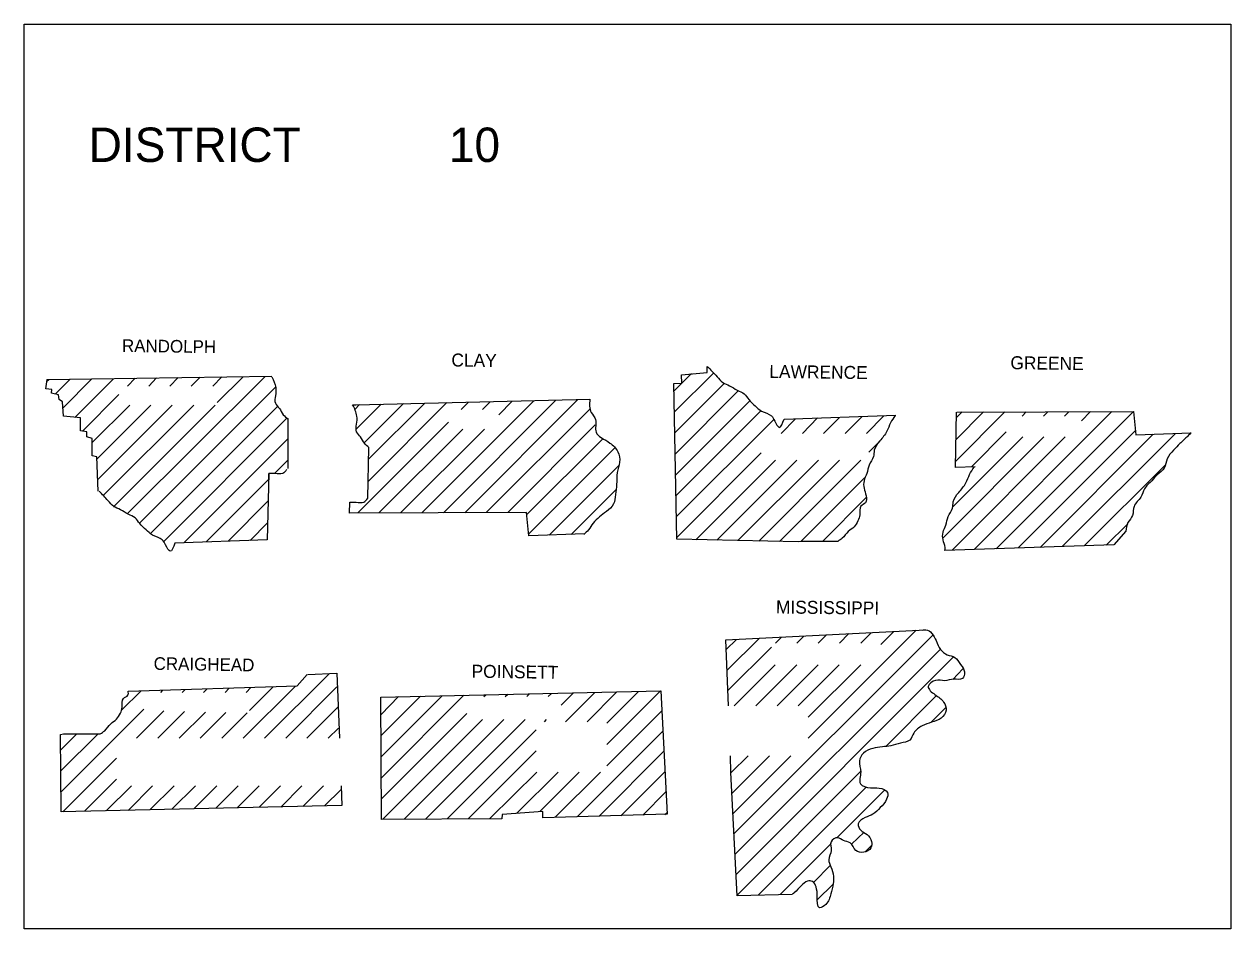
# Model space of a CAD drawing. Extents: x 23481 to 28196, y 1325020 to 1327623.
# Drawn here: x 27792.5 to 28192.5, y 1325389.6 to 1325689.6 of the extents above; entities that cross this region are included whole.
import ezdxf

# ---------------------------------------------------------------- set-up
doc = ezdxf.new("R2010")
doc.units = 0
doc.layers.add('S_ELECTRIC_UTILITIES_ANNOT', color=7, linetype='Continuous')

msp = doc.modelspace()

# ---------------------------------------------------------------- linework, layer by layer
at = {"layer": 'S_ELECTRIC_UTILITIES_ANNOT'}
msp.add_lwpolyline([(27792.46, 1325389.62), (27792.46, 1325689.62), (28192.46, 1325689.62), (28192.46, 1325389.62)], close=True, dxfattribs=at)
for points in [[(28049.06, 1325517.92), (28008.76, 1325518.82), (28007.86, 1325570.42), (28010.46, 1325570.52), (28010.36, 1325573.32), (28018.86, 1325574.12), (28018.86, 1325576.12)], [(27799.96, 1325571.82), (27874.56, 1325572.92)], [(27805.36, 1325562.42), (27814.86, 1325572.02)], [(27809.26, 1325559.22), (27822.06, 1325572.02)], [(27826.76, 1325527.32), (27872.36, 1325572.82)], [(27826.76, 1325569.62), (27829.26, 1325572.22)], [(27833.76, 1325569.62), (27836.36, 1325572.32)], [(27840.76, 1325569.62), (27843.56, 1325572.42)], [(27847.86, 1325569.62), (27850.76, 1325572.52)], [(27854.96, 1325569.62), (27857.96, 1325572.62)], [(27856.46, 1325564.12), (27865.06, 1325572.72)], [(28007.86, 1325567.92), (28010.46, 1325570.52), (28013.66, 1325573.72)], [(28008.06, 1325561.02), (28020.96, 1325573.92)], [(27816.96, 1325534.72), (27816.56, 1325546.12), (27814.96, 1325546.42), (27815.06, 1325552.22), (27813.26, 1325552.72), (27813.26, 1325554.42), (27811.16, 1325554.72), (27811.16, 1325559.02), (27805.46, 1325559.62), (27805.16, 1325564.42), (27804.06, 1325565.12), (27803.86, 1325566.72), (27801.56, 1325567.22), (27801.66, 1325568.42), (27799.66, 1325568.72), (27800.06, 1325571.82)], [(27799.96, 1325571.22), (27800.66, 1325571.82)], [(27802.86, 1325567.02), (27807.76, 1325571.92)], [(27830.76, 1325524.22), (27875.76, 1325569.22)], [(28008.16, 1325554.12), (28024.46, 1325570.42)], [(28008.36, 1325547.12), (28029.16, 1325568.02)], [(27811.76, 1325554.62), (27823.86, 1325566.82)], [(27901.36, 1325563.42), (27902.36, 1325563.42), (27979.96, 1325565.22)], [(27906.56, 1325538.12), (27932.56, 1325564.12)], [(27924.26, 1325527.52), (27961.46, 1325564.72)], [(27931.46, 1325527.62), (27968.76, 1325564.92)], [(27937.36, 1325561.82), (27939.76, 1325564.22)], [(27938.56, 1325527.62), (27975.96, 1325565.12)], [(27944.36, 1325561.82), (27946.96, 1325564.42)], [(27949.76, 1325560.12), (27954.26, 1325564.62)], [(28008.46, 1325540.22), (28032.96, 1325564.72)], [(27815.06, 1325550.92), (27827.46, 1325563.32)], [(27816.66, 1325545.52), (27834.46, 1325563.32)], [(27816.86, 1325538.62), (27841.56, 1325563.32)], [(27818.76, 1325533.42), (27848.66, 1325563.32)], [(27822.06, 1325529.62), (27822.16, 1325529.72), (27855.76, 1325563.32)], [(27834.46, 1325520.82), (27876.46, 1325562.82)], [(27902.06, 1325561.82), (27903.66, 1325563.52)], [(27902.66, 1325555.42), (27910.86, 1325563.62)], [(27905.16, 1325550.82), (27918.16, 1325563.82)], [(27906.66, 1325545.32), (27925.26, 1325563.92)], [(27945.66, 1325527.72), (27980.16, 1325562.22)], [(28008.56, 1325533.32), (28036.66, 1325561.42)], [(28101.16, 1325544.62), (28117.56, 1325561.02)], [(28101.16, 1325542.62), (28101.56, 1325560.92)], [(28101.36, 1325551.92), (28110.46, 1325561.02)], [(28101.56, 1325559.22), (28103.36, 1325561.02)], [(28101.66, 1325560.92), (28160.16, 1325561.22), (28160.96, 1325553.42), (28179.26, 1325554.12)], [(28107.36, 1325515.42), (28152.96, 1325561.12)], [(28114.66, 1325515.62), (28160.16, 1325561.22)], [(28123.26, 1325559.62), (28124.56, 1325561.02)], [(28130.36, 1325559.62), (28131.76, 1325561.02)], [(28137.36, 1325559.62), (28138.76, 1325561.02)], [(28142.96, 1325558.12), (28145.96, 1325561.12)], [(27838.76, 1325518.12), (27879.56, 1325558.92)], [(27879.86, 1325558.52), (27879.86, 1325542.22)], [(27903.06, 1325527.52), (27933.16, 1325557.62)], [(27952.76, 1325527.72), (27981.76, 1325556.72)], [(28008.66, 1325526.32), (28040.96, 1325558.52)], [(28043.36, 1325553.92), (28048.16, 1325558.72)], [(28044.36, 1325558.62), (28081.46, 1325559.92)], [(28050.46, 1325553.92), (28055.46, 1325559.02)], [(28057.46, 1325553.92), (28062.76, 1325559.22)], [(28064.66, 1325553.92), (28070.16, 1325559.42)], [(28071.66, 1325553.92), (28077.46, 1325559.72)], [(27845.46, 1325517.72), (27879.86, 1325552.12)], [(27910.06, 1325527.52), (27937.86, 1325555.32)], [(27917.26, 1325527.52), (27945.06, 1325555.32)], [(27959.06, 1325527.02), (27984.26, 1325552.12)], [(28097.06, 1325519.32), (28130.46, 1325552.72)], [(28100.06, 1325515.22), (28137.56, 1325552.72)], [(28100.36, 1325529.72), (28123.46, 1325552.72)], [(28106.46, 1325542.82), (28117.96, 1325554.42)], [(28121.96, 1325515.92), (28160.76, 1325554.72)], [(28129.26, 1325516.12), (28166.76, 1325553.62)], [(28136.56, 1325516.42), (28174.06, 1325553.92)], [(27906.36, 1325532.42), (27906.76, 1325549.22)], [(27959.76, 1325520.62), (27988.26, 1325549.12)], [(28072.46, 1325547.72), (28075.66, 1325550.92)], [(27875.46, 1325540.62), (27879.86, 1325545.02)], [(28008.76, 1325519.42), (28036.76, 1325547.42)], [(28015.16, 1325518.62), (28041.56, 1325545.02)], [(28022.06, 1325518.52), (28048.56, 1325545.02)], [(28029.06, 1325518.42), (28055.76, 1325545.02)], [(28035.96, 1325518.22), (28062.76, 1325545.02)], [(28042.86, 1325518.12), (28069.76, 1325545.02)], [(27873.56, 1325536.92), (27873.56, 1325540.62), (27873.06, 1325518.62)], [(27966.46, 1325520.22), (27989.56, 1325543.32)], [(28107.66, 1325542.82), (28101.16, 1325542.62)], [(28143.86, 1325516.62), (28170.66, 1325543.42)], [(27852.76, 1325517.92), (27873.56, 1325538.72), (27873.56, 1325538.72)], [(28049.96, 1325518.12), (28071.06, 1325539.22)], [(27973.76, 1325520.42), (27988.66, 1325535.32)], [(28057.06, 1325518.12), (28071.56, 1325532.62)], [(27860.06, 1325518.22), (27873.36, 1325531.52)], [(27900.36, 1325527.42), (27900.46, 1325531.12)], [(27867.36, 1325518.42), (27873.16, 1325524.22)], [(27978.16, 1325520.62), (27959.76, 1325519.92), (27958.96, 1325527.72), (27900.46, 1325527.42)], [(28157.66, 1325521.52), (28153.66, 1325516.92), (28097.66, 1325515.12)], [(28151.16, 1325516.82), (28158.26, 1325523.92)], [(27873.06, 1325518.62), (27842.46, 1325517.52)], [(28062.16, 1325518.12), (28049.96, 1325518.12), (28049.06, 1325517.92)], [(28025.06, 1325485.42), (28091.36, 1325488.82)], [(28052.36, 1325452.82), (28088.16, 1325488.62)], [(28076.46, 1325483.92), (28080.76, 1325488.22)], [(28025.96, 1325463.62), (28025.06, 1325485.42)], [(28025.16, 1325482.22), (28028.56, 1325485.62)], [(28025.46, 1325475.42), (28036.06, 1325485.92)], [(28027.76, 1325421.12), (28093.56, 1325486.92), (28093.66, 1325487.02)], [(28041.56, 1325484.32), (28043.56, 1325486.32)], [(28048.56, 1325484.32), (28050.96, 1325486.72)], [(28055.66, 1325484.32), (28058.46, 1325487.12)], [(28062.76, 1325484.32), (28065.86, 1325487.52)], [(28069.76, 1325484.32), (28073.26, 1325487.82)], [(28025.76, 1325468.62), (28040.16, 1325483.02)], [(28028.06, 1325414.32), (28096.16, 1325482.42)], [(28027.86, 1325463.62), (28041.46, 1325477.22)], [(28028.46, 1325407.62), (28100.56, 1325479.82)], [(28034.96, 1325463.62), (28048.56, 1325477.22)], [(28042.06, 1325463.62), (28055.66, 1325477.22)], [(28049.06, 1325463.62), (28062.66, 1325477.22)], [(28052.36, 1325459.82), (28069.76, 1325477.22)], [(27826.96, 1325468.42), (27882.96, 1325470.22), (27886.26, 1325474.02)], [(27872.16, 1325452.82), (27893.56, 1325474.22)], [(27886.46, 1325473.92), (27896.06, 1325474.42)], [(27896.06, 1325474.42), (27896.96, 1325452.82)], [(28100.26, 1325472.32), (28103.66, 1325475.82)], [(27824.76, 1325462.12), (27831.26, 1325468.52)], [(27837.76, 1325468.02), (27838.46, 1325468.72)], [(27844.86, 1325468.02), (27845.76, 1325468.92)], [(27851.96, 1325468.02), (27853.16, 1325469.22)], [(27859.06, 1325468.02), (27860.46, 1325469.42)], [(27865.06, 1325452.82), (27882.36, 1325470.12)], [(27866.06, 1325468.02), (27867.66, 1325469.62)], [(27867.16, 1325462.02), (27875.06, 1325469.92)], [(27879.16, 1325452.82), (27896.16, 1325469.92)], [(27910.66, 1325466.42), (28003.56, 1325468.52)], [(27971.96, 1325458.32), (27981.66, 1325468.02)], [(27979.06, 1325458.32), (27988.96, 1325468.22)], [(27985.56, 1325450.72), (28003.36, 1325468.52)], [(27985.56, 1325457.82), (27996.16, 1325468.32)], [(28003.56, 1325468.52), (28005.56, 1325427.62)], [(27910.96, 1325425.92), (27910.66, 1325466.42)], [(27910.76, 1325453.72), (27923.86, 1325466.82)], [(27910.76, 1325460.72), (27916.56, 1325466.62)], [(27910.86, 1325446.72), (27931.06, 1325466.92)], [(27910.96, 1325439.72), (27938.26, 1325467.12)], [(27944.86, 1325466.62), (27945.46, 1325467.22)], [(27951.96, 1325466.62), (27952.76, 1325467.42)], [(27959.06, 1325466.62), (27959.96, 1325467.52)], [(27966.16, 1325466.62), (27967.26, 1325467.72)], [(27970.46, 1325463.82), (27974.46, 1325467.82)], [(28078.06, 1325450.12), (28094.76, 1325466.92)], [(27804.76, 1325435.02), (27832.16, 1325462.42)], [(27829.66, 1325452.82), (27838.76, 1325461.92)], [(27836.76, 1325452.82), (27845.66, 1325461.72)], [(27843.86, 1325452.82), (27852.56, 1325461.52)], [(27850.86, 1325452.82), (27859.36, 1325461.32)], [(27857.96, 1325452.82), (27866.36, 1325461.22)], [(27886.16, 1325452.82), (27896.46, 1325463.12)], [(27910.96, 1325432.72), (27939.26, 1325461.02)], [(27985.56, 1325443.72), (28003.86, 1325461.92)], [(28092.96, 1325458.02), (28097.96, 1325463.02)], [(27893.26, 1325452.82), (27896.66, 1325456.22)], [(27911.36, 1325426.02), (27944.36, 1325459.02)], [(27918.46, 1325426.02), (27951.46, 1325459.02)], [(27925.46, 1325426.02), (27958.56, 1325459.02)], [(27964.96, 1325458.32), (27965.66, 1325459.02)], [(27804.56, 1325454.12), (27805.46, 1325454.32), (27817.66, 1325454.32)], [(27804.76, 1325428.42), (27804.56, 1325454.12)], [(27804.66, 1325442.02), (27816.96, 1325454.32)], [(27804.66, 1325449.02), (27809.96, 1325454.32)], [(27932.66, 1325426.12), (27962.16, 1325455.62)], [(27975.76, 1325426.82), (28004.16, 1325455.22)], [(27939.66, 1325426.12), (27962.16, 1325448.62)], [(27982.96, 1325426.92), (28004.56, 1325448.52)], [(27805.26, 1325428.42), (27823.06, 1325446.22)], [(28028.76, 1325400.62), (28026.76, 1325441.52), (28026.56, 1325447.02)], [(28026.86, 1325441.42), (28032.46, 1325447.02)], [(28027.16, 1325434.62), (28039.56, 1325447.02)], [(28027.46, 1325427.92), (28046.56, 1325447.02)], [(27946.76, 1325426.12), (27962.36, 1325441.62)], [(27955.66, 1325427.92), (27969.46, 1325441.62)], [(27963.36, 1325428.52), (27976.46, 1325441.62)], [(27968.46, 1325426.62), (27983.56, 1325441.62)], [(27990.26, 1325427.12), (28004.86, 1325441.72)], [(28028.76, 1325400.82), (28069.66, 1325441.82)], [(27812.46, 1325428.62), (27823.06, 1325439.22)], [(27819.66, 1325428.72), (27828.06, 1325437.02)], [(27826.96, 1325428.92), (27835.06, 1325437.02)], [(27834.16, 1325429.12), (27842.16, 1325437.02)], [(27841.46, 1325429.32), (27849.26, 1325437.02)], [(27848.66, 1325429.42), (27856.36, 1325437.02)], [(27855.96, 1325429.62), (27863.36, 1325437.02)], [(27863.16, 1325429.82), (27870.36, 1325437.02)], [(27870.36, 1325429.92), (27877.46, 1325437.02)], [(27877.56, 1325430.02), (27884.56, 1325437.02)], [(27884.86, 1325430.22), (27891.66, 1325437.02)], [(27897.56, 1325437.02), (27897.76, 1325430.52)], [(28035.76, 1325400.82), (28071.56, 1325436.62)], [(27892.06, 1325430.42), (27897.56, 1325435.82)], [(27997.56, 1325427.32), (28005.16, 1325435.02)], [(28061.96, 1325419.92), (28077.76, 1325435.72)], [(27897.76, 1325430.52), (27804.76, 1325428.42)], [(28005.56, 1325427.62), (27964.36, 1325426.42), (27964.36, 1325428.52), (27950.96, 1325427.52), (27950.86, 1325426.12), (27910.96, 1325425.92)], [(28004.86, 1325427.52), (28005.56, 1325428.22)], [(28066.76, 1325417.72), (28070.86, 1325421.72)], [(28043.06, 1325401.02), (28059.96, 1325417.92)], [(28071.36, 1325415.22), (28073.36, 1325417.22)], [(28054.16, 1325405.02), (28059.76, 1325410.72)], [(28055.36, 1325399.22), (28060.66, 1325404.42)], [(28047.06, 1325401.02), (28028.76, 1325400.62)]]:
    msp.add_lwpolyline(points, dxfattribs=at)
for points in [[(28018.86, 1325576.12), (28022.16, 1325572.72), (28024.06, 1325570.82), (28026.26, 1325569.72), (28028.86, 1325568.22), (28031.16, 1325567.02), (28032.66, 1325565.12), (28034.76, 1325563.02), (28036.86, 1325561.32), (28040.16, 1325559.72), (28041.26, 1325558.02), (28042.76, 1325555.92), (28044.36, 1325558.62)], [(27874.56, 1325572.62), (27875.86, 1325569.12), (27875.76, 1325566.42), (27875.76, 1325563.92), (27877.06, 1325562.22), (27878.36, 1325560.12), (27880.06, 1325558.62)], [(27979.96, 1325565.22), (27980.46, 1325560.82), (27981.86, 1325558.52), (27982.06, 1325554.32), (27983.76, 1325552.52), (27986.66, 1325550.72), (27989.26, 1325547.82), (27989.86, 1325544.42), (27989.06, 1325540.92), (27988.86, 1325537.02), (27988.46, 1325533.62), (27987.86, 1325530.52), (27985.46, 1325528.02), (27983.16, 1325526.22), (27981.06, 1325524.12), (27979.56, 1325521.92), (27977.96, 1325520.42)], [(27979.96, 1325565.22), (27980.46, 1325560.82), (27981.86, 1325558.52), (27982.06, 1325554.32), (27983.76, 1325552.52), (27986.66, 1325550.72), (27989.26, 1325547.82), (27989.86, 1325544.42), (27989.06, 1325540.92), (27988.86, 1325537.02), (27988.46, 1325533.62), (27987.86, 1325530.52), (27985.46, 1325528.02), (27983.16, 1325526.22), (27981.06, 1325524.12), (27979.56, 1325521.92), (27977.96, 1325520.42)], [(27906.76, 1325549.22), (27905.26, 1325550.62), (27903.96, 1325552.72), (27902.66, 1325554.42), (27902.66, 1325556.92), (27902.76, 1325559.62), (27901.36, 1325563.42)], [(28081.16, 1325559.82), (28079.66, 1325557.42), (28078.46, 1325554.62), (28076.06, 1325551.42), (28074.26, 1325548.32), (28073.96, 1325546.22), (28072.56, 1325543.42), (28071.76, 1325540.62), (28070.86, 1325538.22), (28070.86, 1325535.72), (28071.56, 1325533.22), (28071.36, 1325530.92), (28069.86, 1325529.82), (28069.46, 1325526.92), (28068.86, 1325524.92), (28067.56, 1325522.92), (28065.66, 1325521.42), (28063.66, 1325519.12), (28062.16, 1325518.12)], [(28179.26, 1325554.12), (28178.16, 1325553.02), (28175.56, 1325550.52), (28173.46, 1325548.32), (28171.36, 1325545.52), (28170.36, 1325542.42), (28168.06, 1325540.22), (28166.26, 1325538.22), (28163.86, 1325535.52), (28162.66, 1325532.82), (28160.36, 1325529.72), (28159.86, 1325526.72), (28158.36, 1325524.32), (28157.66, 1325521.52)], [(28179.26, 1325554.12), (28178.16, 1325553.02), (28175.56, 1325550.52), (28173.46, 1325548.32), (28171.36, 1325545.52), (28170.36, 1325542.42), (28168.06, 1325540.22), (28166.26, 1325538.22), (28163.86, 1325535.52), (28162.66, 1325532.82), (28160.36, 1325529.72), (28159.86, 1325526.72), (28158.36, 1325524.32), (28157.66, 1325521.52)], [(27879.46, 1325541.92), (27878.16, 1325540.62), (27875.66, 1325540.62), (27873.56, 1325540.62)], [(28097.66, 1325515.12), (28097.76, 1325516.12), (28097.06, 1325518.62), (28097.06, 1325521.12), (28097.96, 1325523.52), (28098.76, 1325526.32), (28100.16, 1325529.12), (28100.46, 1325531.22), (28102.26, 1325534.32), (28104.66, 1325537.52), (28105.86, 1325540.32), (28107.36, 1325542.72)], [(27842.46, 1325517.52), (27840.86, 1325514.82), (27839.36, 1325516.92), (27838.26, 1325518.62), (27834.96, 1325520.22), (27832.86, 1325521.92), (27830.76, 1325524.02), (27829.26, 1325525.92), (27826.96, 1325527.12), (27824.36, 1325528.62), (27822.16, 1325529.72), (27820.26, 1325531.62), (27817.36, 1325534.72)], [(27900.46, 1325531.12), (27902.56, 1325531.12), (27905.06, 1325531.12), (27906.36, 1325532.42)], [(28090.26, 1325488.72), (28091.36, 1325488.82), (28094.76, 1325485.22), (28096.26, 1325482.22), (28098.46, 1325480.52), (28100.96, 1325479.62), (28102.86, 1325477.32), (28104.16, 1325474.82), (28103.46, 1325472.62), (28100.66, 1325472.42), (28097.56, 1325471.92), (28094.56, 1325472.02), (28092.16, 1325470.02), (28094.36, 1325467.32), (28097.26, 1325464.82), (28098.06, 1325462.12), (28096.46, 1325459.52), (28093.26, 1325458.12), (28090.16, 1325456.92), (28087.36, 1325454.52), (28086.06, 1325452.22), (28082.96, 1325451.22), (28079.76, 1325450.32), (28076.96, 1325450.02), (28073.76, 1325449.42), (28070.66, 1325447.92), (28069.36, 1325445.32), (28069.76, 1325441.62), (28069.66, 1325437.72), (28072.96, 1325436.42), (28075.86, 1325436.32), (28078.66, 1325434.82), (28078.36, 1325432.62), (28076.26, 1325429.82), (28073.76, 1325427.62), (28071.26, 1325426.52), (28068.96, 1325424.42), (28069.76, 1325422.32), (28071.86, 1325420.92), (28073.36, 1325418.62), (28073.16, 1325416.52), (28070.76, 1325415.02), (28068.16, 1325415.62), (28066.26, 1325418.12), (28064.06, 1325418.92), (28062.16, 1325419.82), (28059.96, 1325418.52), (28059.96, 1325415.62), (28059.16, 1325412.52), (28059.86, 1325410.22), (28060.76, 1325407.02), (28060.66, 1325404.62), (28059.86, 1325401.22), (28058.16, 1325397.72), (28056.16, 1325396.62), (28055.36, 1325400.42), (28054.96, 1325403.52), (28053.76, 1325405.32), (28052.16, 1325405.42), (28050.06, 1325403.92), (28047.76, 1325401.62), (28047.16, 1325401.12)], [(28090.26, 1325488.72), (28091.36, 1325488.82), (28094.76, 1325485.22), (28096.26, 1325482.22), (28098.46, 1325480.52), (28100.96, 1325479.62), (28102.86, 1325477.32), (28104.16, 1325474.82), (28103.46, 1325472.62), (28100.66, 1325472.42), (28097.56, 1325471.92), (28094.56, 1325472.02), (28092.16, 1325470.02), (28094.36, 1325467.32), (28097.26, 1325464.82), (28098.06, 1325462.12), (28096.46, 1325459.52), (28093.26, 1325458.12), (28090.16, 1325456.92), (28087.36, 1325454.52), (28086.06, 1325452.22), (28082.96, 1325451.22), (28079.76, 1325450.32), (28076.96, 1325450.02), (28073.76, 1325449.42), (28070.66, 1325447.92), (28069.36, 1325445.32), (28069.76, 1325441.62), (28069.66, 1325437.72), (28072.96, 1325436.42), (28075.86, 1325436.32), (28078.66, 1325434.82), (28078.36, 1325432.62), (28076.26, 1325429.82), (28073.76, 1325427.62), (28071.26, 1325426.52), (28068.96, 1325424.42), (28069.76, 1325422.32), (28071.86, 1325420.92), (28073.36, 1325418.62), (28073.16, 1325416.52), (28070.76, 1325415.02), (28068.16, 1325415.62), (28066.26, 1325418.12), (28064.06, 1325418.92), (28062.16, 1325419.82), (28059.96, 1325418.52), (28059.96, 1325415.62), (28059.16, 1325412.52), (28059.86, 1325410.22), (28060.76, 1325407.02), (28060.66, 1325404.62), (28059.86, 1325401.22), (28058.16, 1325397.72), (28056.16, 1325396.62), (28055.36, 1325400.42), (28054.96, 1325403.52), (28053.76, 1325405.32), (28052.16, 1325405.42), (28050.06, 1325403.92), (28047.76, 1325401.62), (28047.16, 1325401.12)], [(27817.66, 1325454.32), (27819.16, 1325455.32), (27821.16, 1325457.62), (27823.06, 1325459.12), (27824.36, 1325461.12), (27824.96, 1325463.12), (27825.36, 1325466.02), (27826.86, 1325467.12), (27826.96, 1325468.42)]]:
    msp.add_spline(points, degree=3, dxfattribs=at)

# ---------------------------------------------------------------- texts
for s, p in [('DISTRICT', (27813.86, 1325643.92)), ('10', (27933.26, 1325643.92))]:
    msp.add_text(s, height=11.4, dxfattribs=at).set_placement(p)
for s, height, rotation, p in [('RANDOLPH', 4.201, 359.2583, (27824.86, 1325580.92)), ('CLAY', 4.3, 359.2258, (27934.06, 1325576.12)), ('LAWRENCE', 4.301, 359.2678, (28039.46, 1325572.32)), ('GREENE', 4.301, 359.2361, (28119.36, 1325575.22)), ('MISSISSIPPI', 4.2996, 359.3097, (28041.66, 1325494.22)), ('CRAIGHEAD', 4.201, 359.1159, (27835.36, 1325475.52)), ('POINSETT', 4.3, 359.1987, (27940.76, 1325472.92))]:
    msp.add_text(s, height=height, rotation=rotation, dxfattribs=at).set_placement(p)

doc.saveas('drawing.dxf')
